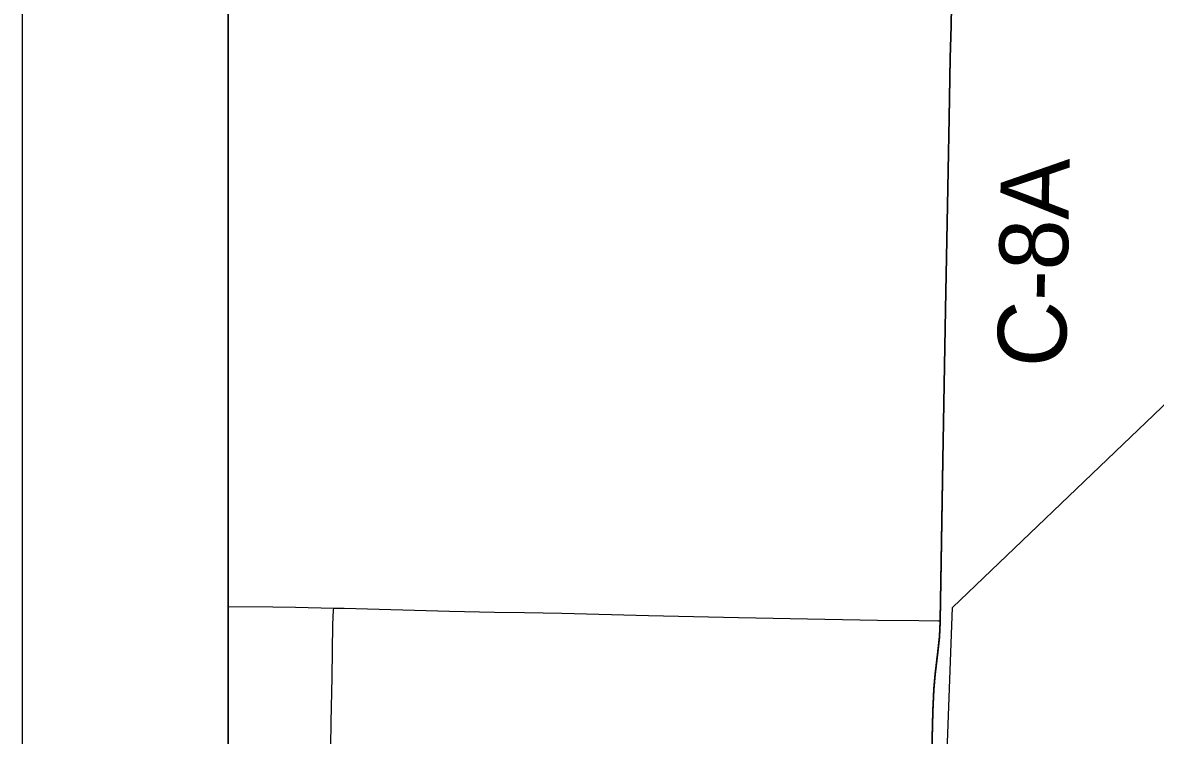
# Model space of a CAD drawing. Extents: x -483 to 680, y 0 to 440.
# Drawn here: x 37.11 to 83.98, y 148.34 to 177.85 of the extents above; entities that cross this region are included whole.
import ezdxf

# ---------------------------------------------------------------- set-up
doc = ezdxf.new("R2010")
doc.units = 0
for name, color, linetype in [('GM_X_County_Road', 7, 'Continuous'), ('GM_X_County_Road_Text', 7, 'Continuous'), ('GM_X_Minor_River', 7, 'Continuous'), ('GM_X_Township_Road', 7, 'Continuous'), ('SH_Cut_Line', 7, 'Continuous'), ('SH_Text', 7, 'Continuous')]:
    doc.layers.add(name, color=color, linetype=linetype)

msp = doc.modelspace()

# ---------------------------------------------------------------- linework, layer by layer
at = {"layer": 'GM_X_County_Road'}
for points in [[(75.532, 177.624), (75.533, 177.672), (75.602, 182.027), (75.661, 185.894)], [(75.09, 153.079), (75.127, 155.517), (75.19, 159.717), (75.299, 165.94), (75.407, 171.696), (75.456, 173.874), (75.504, 176.363), (75.532, 177.624)]]:
    msp.add_lwpolyline(points, dxfattribs=at)
at = {"layer": 'GM_X_Minor_River'}
msp.add_lwpolyline([(74.642, 128.314), (75.587, 153.634), (193.508, 266.565)], dxfattribs=at)
at = {"layer": 'GM_X_Township_Road'}
for points in [[(75.532, 177.624), (75.533, 177.672), (75.602, 182.027), (75.661, 185.894)], [(75.09, 153.079), (75.127, 155.517), (75.19, 159.717), (75.299, 165.94), (75.407, 171.696), (75.456, 173.874), (75.504, 176.363), (75.532, 177.624)], [(45.608, 153.679), (47.461, 153.658), (48.393, 153.645), (49.978, 153.612)], [(49.847, 146.864), (49.868, 148.884), (49.908, 150.749), (49.945, 152.928), (49.973, 153.518), (49.978, 153.612)], [(49.978, 153.612), (50.412, 153.603), (54.763, 153.484), (56.627, 153.447), (57.87, 153.425), (59.424, 153.393), (62.997, 153.306), (66.726, 153.222), (70.301, 153.157), (72.476, 153.114), (74.186, 153.101), (74.996, 153.081), (75.09, 153.079)], [(74.213, 128.308), (74.313, 130.414), (74.338, 131.271), (74.392, 132.825), (74.399, 133.914), (74.396, 134.301), (74.392, 134.692), (74.378, 135.625), (74.37, 135.936), (74.375, 137.025), (74.407, 138.891), (74.448, 140.914), (74.494, 142.158), (74.669, 145.265), (74.715, 146.509), (74.783, 149.308), (74.825, 150.241), (74.874, 150.861), (74.99, 151.787), (75.057, 152.406), (75.089, 153.027), (75.09, 153.079)]]:
    msp.add_lwpolyline(points, dxfattribs=at)
at = {"layer": 'SH_Cut_Line'}
for points in [[(45.608, 281.486), (45.608, 55.95), (373.798, 55.95)], [(74.704, 146.536), (74.771, 149.336), (74.813, 150.268), (74.863, 150.888), (74.978, 151.815), (75.045, 152.434), (75.078, 153.055), (75.078, 153.106), (75.116, 155.544), (75.178, 159.745), (75.287, 165.968), (75.396, 171.724), (75.444, 173.902), (75.492, 176.391), (75.521, 177.7), (75.59, 182.054)], [(75.59, 182.054), (75.521, 177.7), (75.492, 176.391), (75.444, 173.902), (75.396, 171.724), (75.287, 165.968), (75.178, 159.745), (75.116, 155.544), (75.078, 153.106), (75.078, 153.055), (75.045, 152.434), (74.978, 151.815), (74.863, 150.888), (74.813, 150.268), (74.771, 149.336), (74.704, 146.536)]]:
    msp.add_lwpolyline(points, dxfattribs=at)
at = {"layer": 'SH_Text'}
for points in [[(37.108, 404.45), (394.108, 404.45), (394.108, 47.45), (37.108, 47.45)], [(45.608, 395.95), (385.608, 395.95), (385.608, 55.95), (45.608, 55.95)]]:
    msp.add_lwpolyline(points, close=True, dxfattribs=at)

# ---------------------------------------------------------------- texts
at = {"layer": 'GM_X_County_Road_Text'}
msp.add_text('C-8A', height=2.8409, rotation=88.9308, dxfattribs=at).set_placement((80.272, 163.564))

doc.saveas('drawing.dxf')
